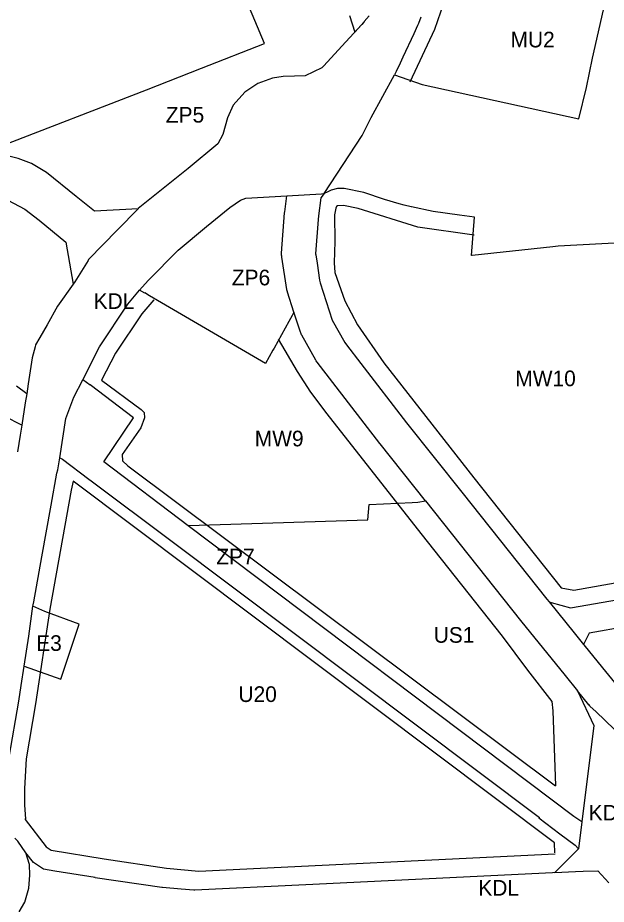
# Model space of a CAD drawing. Extents: x 7428103 to 7431580, y 5545880 to 5549002.
# Drawn here: x 7429131.7 to 7429340.3, y 5547973.7 to 5548288 of the extents above; entities that cross this region are included whole.
import ezdxf

# ---------------------------------------------------------------- set-up
doc = ezdxf.new("R2010")
doc.units = 0
for name, color, linetype in [('CZ_L_linie rozgraniczające tereny o różnym przeznaczeniu oraz różnych warunkach ich zabudowy i zagospodarowania', 7, 'Continuous'), ('CZ_L_maksymalne nieprzekraczalne linie zabudowy', 7, 'Continuous'), ('CZ_L_opisy_linie rozgraniczające tereny o różnym przeznaczeniu oraz różnych warunkach ich zabudowy i zagospodarowania', 7, 'Continuous')]:
    doc.layers.add(name, color=color, linetype=linetype)

msp = doc.modelspace()

# ---------------------------------------------------------------- linework, layer by layer
at = {"layer": 'CZ_L_linie rozgraniczające tereny o różnym przeznaczeniu oraz różnych warunkach ich zabudowy i zagospodarowania'}
for p, q in [((7429219.15, 5548278.95), (7429209.95, 5548300.95)), ((7429335.47, 5548273.67), (7429339.93, 5548293.42)), ((7429249.28, 5548288.79), (7429251.17, 5548282.96)), ((7429256.3, 5548288.71), (7429254.54, 5548286.65)), ((7429274.55, 5548288.21), (7429273.79, 5548285.99)), ((7429253.66, 5548285.6), (7429246.64, 5548277.96)), ((7429251.17, 5548282.96), (7429254.47, 5548286.56)), ((7429254.46, 5548286.46), (7429253.66, 5548285.6)), ((7429254.47, 5548286.56), (7429254.46, 5548286.46)), ((7429254.54, 5548286.65), (7429254.47, 5548286.56)), ((7429273.44, 5548285.25), (7429272.08, 5548282.34)), ((7429273.79, 5548285.99), (7429273.44, 5548285.25)), ((7429272.08, 5548282.34), (7429268.23, 5548274.09)), ((7429196.87, 5548270.18), (7429219.15, 5548278.95)), ((7429246.64, 5548277.96), (7429240.18, 5548270.95)), ((7429268.23, 5548274.09), (7429267.23, 5548271.95)), ((7429333.33, 5548263.33), (7429335.47, 5548273.67)), ((7429177.42, 5548262.52), (7429196.87, 5548270.18)), ((7429239.53, 5548270.24), (7429233.62, 5548267.48)), ((7429240.18, 5548270.95), (7429239.53, 5548270.24)), ((7429267.23, 5548271.95), (7429265.83, 5548268.95)), ((7429222.05, 5548266.67), (7429216.84, 5548264.76)), ((7429225.79, 5548267.17), (7429222.05, 5548266.67)), ((7429229.87, 5548267.33), (7429225.79, 5548267.17)), ((7429233.62, 5548267.48), (7429229.87, 5548267.33)), ((7429257.04, 5548252.68), (7429265.27, 5548267.75)), ((7429265.83, 5548268.95), (7429265.27, 5548267.75)), ((7429265.27, 5548267.75), (7429275.08, 5548264.33)), ((7429216.84, 5548264.76), (7429212.19, 5548261.67)), ((7429275.08, 5548264.33), (7429330.57, 5548252.2)), ((7429330.57, 5548252.2), (7429333.33, 5548263.33)), ((7429124.64, 5548242.13), (7429177.42, 5548262.52)), ((7429212.19, 5548261.67), (7429208.11, 5548257.07)), ((7429208.11, 5548257.07), (7429206.08, 5548252.55)), ((7429206.08, 5548252.55), (7429204.44, 5548246.68)), ((7429253.81, 5548246.23), (7429257.04, 5548252.68)), ((7429204.44, 5548246.68), (7429202.7, 5548243.37)), ((7429240.31, 5548225.7), (7429253.81, 5548246.23)), ((7429202.7, 5548243.37), (7429192.13, 5548234.58)), ((7429131.95, 5548238.17), (7429125.06, 5548239.73)), ((7429136.62, 5548236.39), (7429131.95, 5548238.17)), ((7429141.88, 5548233.19), (7429136.62, 5548236.39)), ((7429192.13, 5548234.58), (7429174.45, 5548220.38)), ((7429152.47, 5548224.68), (7429141.88, 5548233.19)), ((7429227.16, 5548224.92), (7429239.38, 5548225.64)), ((7429240.31, 5548225.7), (7429239.17, 5548224.19)), ((7429239.38, 5548225.64), (7429240.31, 5548225.7)), ((7429241.42, 5548226.24), (7429240.31, 5548225.7)), ((7429242.77, 5548226.9), (7429241.42, 5548226.24)), ((7429245.07, 5548227.45), (7429242.77, 5548226.9)), ((7429247.45, 5548227.46), (7429245.07, 5548227.45)), ((7429254.38, 5548226.13), (7429247.45, 5548227.46)), ((7429261.71, 5548223.63), (7429254.38, 5548226.13)), ((7429128.22, 5548223.31), (7429134.26, 5548220.14)), ((7429158.94, 5548219.41), (7429152.47, 5548224.68)), ((7429206.88, 5548220.73), (7429210.66, 5548223.39)), ((7429210.66, 5548223.39), (7429212.6, 5548224.07)), ((7429212.6, 5548224.07), (7429227.16, 5548224.92)), ((7429226.37, 5548219.22), (7429227.16, 5548224.92)), ((7429239.17, 5548224.19), (7429238.28, 5548217.75)), ((7429266.93, 5548222.09), (7429261.71, 5548223.63)), ((7429268.72, 5548221.56), (7429266.93, 5548222.09)), ((7429134.26, 5548220.14), (7429139.28, 5548216.27)), ((7429174.39, 5548220.32), (7429158.94, 5548219.41)), ((7429174.39, 5548220.32), (7429167.07, 5548212.8)), ((7429174.45, 5548220.38), (7429174.39, 5548220.32)), ((7429198.61, 5548214.05), (7429206.88, 5548220.73)), ((7429225.27, 5548204.54), (7429226.32, 5548218.83)), ((7429226.32, 5548218.83), (7429226.33, 5548218.93)), ((7429226.33, 5548218.93), (7429226.37, 5548219.22)), ((7429271.24, 5548221.03), (7429268.72, 5548221.56)), ((7429271.25, 5548221.03), (7429271.24, 5548221.03)), ((7429278.94, 5548219.37), (7429271.25, 5548221.03)), ((7429288.33, 5548218.06), (7429278.94, 5548219.37)), ((7429139.28, 5548216.27), (7429148.82, 5548208.44)), ((7429238.18, 5548216.48), (7429237.29, 5548204.34)), ((7429238.28, 5548217.75), (7429238.18, 5548216.48)), ((7429293.57, 5548217.32), (7429288.33, 5548218.06)), ((7429292.59, 5548203.71), (7429293.57, 5548217.32)), ((7429167.07, 5548212.8), (7429156.85, 5548202.3)), ((7429188.64, 5548205.64), (7429198.61, 5548214.05)), ((7429148.82, 5548208.44), (7429151.36, 5548193.54)), ((7429321.42, 5548206.8), (7429292.85, 5548203.74)), ((7429323.27, 5548206.99), (7429321.42, 5548206.8)), ((7429351.88, 5548208.53), (7429323.27, 5548206.99)), ((7429177.92, 5548194.9), (7429188.64, 5548205.64)), ((7429225.26, 5548204.24), (7429225.27, 5548204.54)), ((7429225.26, 5548203.85), (7429225.26, 5548204.24)), ((7429225.29, 5548203.46), (7429225.26, 5548203.85)), ((7429225.33, 5548203.17), (7429225.29, 5548203.46)), ((7429227.13, 5548191.66), (7429225.33, 5548203.17)), ((7429237.29, 5548204.34), (7429237.35, 5548203.95)), ((7429237.35, 5548203.95), (7429237.82, 5548200.96)), ((7429292.85, 5548203.74), (7429292.59, 5548203.71)), ((7429156.66, 5548202), (7429151.96, 5548194.39)), ((7429156.85, 5548202.3), (7429156.66, 5548202)), ((7429237.82, 5548200.96), (7429238.75, 5548195.01)), ((7429151.36, 5548193.54), (7429145.83, 5548185.78)), ((7429151.96, 5548194.39), (7429151.36, 5548193.54)), ((7429174.95, 5548191.41), (7429177.92, 5548194.9)), ((7429238.75, 5548195.01), (7429238.91, 5548193.99)), ((7429238.91, 5548193.99), (7429243.16, 5548180.86)), ((7429170.77, 5548186.51), (7429174.95, 5548191.41)), ((7429176.77, 5548190.35), (7429174.95, 5548191.41)), ((7429176.83, 5548190.45), (7429176.77, 5548190.35)), ((7429178.44, 5548189.4), (7429176.83, 5548190.45)), ((7429227.15, 5548191.56), (7429227.13, 5548191.66)), ((7429227.23, 5548191.18), (7429227.15, 5548191.56)), ((7429227.33, 5548190.8), (7429227.23, 5548191.18)), ((7429227.35, 5548190.74), (7429227.33, 5548190.8)), ((7429229.65, 5548183.65), (7429227.35, 5548190.74)), ((7429219.52, 5548165.45), (7429178.44, 5548189.4)), ((7429145.83, 5548185.78), (7429142.18, 5548179.15)), ((7429160.74, 5548171.37), (7429170.77, 5548186.51)), ((7429229, 5548182.44), (7429227.81, 5548180.3)), ((7429229.65, 5548183.65), (7429229, 5548182.44)), ((7429231.93, 5548176.6), (7429229.65, 5548183.65)), ((7429142.18, 5548179.15), (7429139.59, 5548174.69)), ((7429227.81, 5548180.3), (7429222.57, 5548170.88)), ((7429243.16, 5548180.86), (7429247.62, 5548172.91)), ((7429139.59, 5548174.69), (7429138.09, 5548172.03)), ((7429232.04, 5548176.29), (7429231.93, 5548176.6)), ((7429232.19, 5548175.93), (7429232.04, 5548176.29)), ((7429232.37, 5548175.58), (7429232.19, 5548175.93)), ((7429232.41, 5548175.52), (7429232.37, 5548175.58)), ((7429237.37, 5548166.66), (7429232.41, 5548175.52)), ((7429138.09, 5548172.03), (7429137.9, 5548171.31)), ((7429247.62, 5548172.91), (7429248.24, 5548172.1)), ((7429248.24, 5548172.1), (7429253.39, 5548165.43)), ((7429137.9, 5548171.31), (7429136.85, 5548167.43)), ((7429154.76, 5548159.67), (7429160.74, 5548171.37)), ((7429222.16, 5548170.19), (7429219.52, 5548165.45)), ((7429222.57, 5548170.88), (7429222.16, 5548170.19)), ((7429136.85, 5548167.43), (7429135.46, 5548158.26)), ((7429237.53, 5548166.39), (7429237.37, 5548166.66)), ((7429237.75, 5548166.06), (7429237.53, 5548166.39)), ((7429237.85, 5548165.93), (7429237.75, 5548166.06)), ((7429260.1, 5548137.07), (7429237.85, 5548165.93)), ((7429253.39, 5548165.43), (7429269.58, 5548144.43)), ((7429151.58, 5548153.46), (7429154.76, 5548159.67)), ((7429157.39, 5548157.79), (7429154.76, 5548159.67)), ((7429134.92, 5548154.74), (7429131.28, 5548157.46)), ((7429135.46, 5548158.26), (7429134.92, 5548154.74)), ((7429157.43, 5548157.86), (7429157.39, 5548157.79)), ((7429172.75, 5548146.17), (7429157.43, 5548157.86)), ((7429134.92, 5548154.74), (7429134.43, 5548151.49)), ((7429148.74, 5548145.95), (7429151.58, 5548153.46)), ((7429134.43, 5548151.49), (7429133.18, 5548143.55)), ((7429133.18, 5548143.55), (7429127.17, 5548146.62)), ((7429133.18, 5548143.55), (7429132.62, 5548140.01)), ((7429146.63, 5548132.03), (7429148.74, 5548145.95)), ((7429162.3, 5548130.54), (7429172.75, 5548146.17)), ((7429269.58, 5548144.43), (7429289.14, 5548119.8)), ((7429132.62, 5548140.01), (7429131.7, 5548134.17)), ((7429260.16, 5548137), (7429260.1, 5548137.07)), ((7429276.27, 5548116.71), (7429260.16, 5548137)), ((7429145.98, 5548127.79), (7429146.63, 5548132.03)), ((7429146.63, 5548132.03), (7429147.11, 5548131.74)), ((7429147.11, 5548131.74), (7429147.13, 5548131.73)), ((7429147.13, 5548131.73), (7429147.57, 5548131.48)), ((7429147.57, 5548131.48), (7429156.89, 5548124.48)), ((7429145.62, 5548126.54), (7429145.98, 5548127.79)), ((7429192.14, 5548107.87), (7429162.3, 5548130.54)), ((7429143.59, 5548115.26), (7429145.62, 5548126.54)), ((7429156.89, 5548124.48), (7429157.79, 5548123.81)), ((7429157.79, 5548123.81), (7429185.95, 5548102.65)), ((7429289.14, 5548119.8), (7429319.28, 5548081.85)), ((7429140.27, 5548096.83), (7429143.59, 5548115.26)), ((7429255.88, 5548109.98), (7429256.24, 5548115.41)), ((7429256.24, 5548115.41), (7429271.54, 5548116.17)), ((7429271.54, 5548116.17), (7429273.58, 5548116.25)), ((7429273.58, 5548116.25), (7429276.27, 5548116.71)), ((7429276.27, 5548116.71), (7429309.91, 5548074.36)), ((7429192.28, 5548107.99), (7429255.88, 5548109.98)), ((7429192.16, 5548107.88), (7429192.14, 5548107.87)), ((7429192.16, 5548107.88), (7429192.28, 5548107.99)), ((7429328.88, 5548004.86), (7429192.16, 5548107.88)), ((7429185.95, 5548102.65), (7429316.69, 5548004.45)), ((7429137.41, 5548080.93), (7429140.27, 5548096.83)), ((7429137.2, 5548079.81), (7429137.41, 5548080.93)), ((7429319.28, 5548081.85), (7429320.05, 5548080.91)), ((7429320.05, 5548080.91), (7429328.95, 5548069.92)), ((7429320.05, 5548080.91), (7429320.85, 5548080.68)), ((7429320.85, 5548080.68), (7429327.62, 5548078.82)), ((7429327.62, 5548078.82), (7429347.33, 5548082.28)), ((7429135.62, 5548068.81), (7429137.15, 5548079.45)), ((7429137.15, 5548079.45), (7429137.2, 5548079.81)), ((7429141.4, 5548077.55), (7429137.15, 5548079.45)), ((7429153.55, 5548073.02), (7429141.4, 5548077.55)), ((7429383.33, 5548078.47), (7429334.25, 5548069.83)), ((7429309.91, 5548074.36), (7429309.94, 5548074.32)), ((7429309.94, 5548074.32), (7429325.71, 5548054.85)), ((7429146.99, 5548053.54), (7429153.55, 5548073.02)), ((7429134.01, 5548058.16), (7429135.62, 5548068.81)), ((7429328.95, 5548069.92), (7429328.95, 5548069.92)), ((7429328.95, 5548069.92), (7429332.32, 5548065.77)), ((7429334.25, 5548069.83), (7429332.32, 5548065.77)), ((7429332.32, 5548065.77), (7429332.36, 5548065.71)), ((7429332.36, 5548065.71), (7429338.98, 5548057.54)), ((7429132.96, 5548051.26), (7429134.01, 5548058.16)), ((7429134.01, 5548058.16), (7429146.99, 5548053.54)), ((7429338.98, 5548057.54), (7429343.25, 5548052.27)), ((7429325.71, 5548054.85), (7429330.19, 5548049.33)), ((7429132.12, 5548045.7), (7429132.96, 5548051.26)), ((7429334.17, 5548044.42), (7429330.19, 5548049.33)), ((7429330.19, 5548049.33), (7429335.88, 5548037.07)), ((7429128.73, 5548025.84), (7429132.12, 5548045.7)), ((7429334.22, 5548044.36), (7429334.17, 5548044.42)), ((7429334.48, 5548044.06), (7429334.22, 5548044.36)), ((7429334.68, 5548043.87), (7429334.48, 5548044.06)), ((7429336.61, 5548042.02), (7429334.68, 5548043.87)), ((7429346.57, 5548032.47), (7429336.61, 5548042.02)), ((7429335.88, 5548037.07), (7429331.62, 5548002.9)), ((7429316.69, 5548004.45), (7429316.42, 5548004.29)), ((7429316.42, 5548004.29), (7429323.88, 5547998.7)), ((7429331.62, 5548002.9), (7429328.88, 5548004.86)), ((7429331.62, 5548002.9), (7429330.43, 5547993.35)), ((7429323.88, 5547998.7), (7429329.29, 5547994.62)), ((7429131.78, 5547996.01), (7429130.7, 5547997.11)), ((7429134.67, 5547991.98), (7429131.78, 5547996.01)), ((7429330.43, 5547993.35), (7429322.06, 5547984.92)), ((7429329.29, 5547994.62), (7429330.43, 5547993.35)), ((7429135.86, 5547987.85), (7429134.67, 5547991.98)), ((7429137.33, 5547988.53), (7429134.67, 5547991.98)), ((7429136.02, 5547984.04), (7429135.86, 5547987.85)), ((7429140.86, 5547986.15), (7429137.33, 5547988.53)), ((7429144.92, 5547985.47), (7429140.86, 5547986.15)), ((7429135.63, 5547979.44), (7429136.02, 5547984.04)), ((7429144.93, 5547985.47), (7429144.92, 5547985.47)), ((7429159.18, 5547983.13), (7429144.93, 5547985.47)), ((7429159.2, 5547983.13), (7429159.18, 5547983.13)), ((7429159.23, 5547983.12), (7429159.2, 5547983.13)), ((7429182.87, 5547979.65), (7429159.23, 5547983.12)), ((7429321.23, 5547984.88), (7429233.85, 5547980.6)), ((7429322.06, 5547984.92), (7429321.23, 5547984.88)), ((7429322.06, 5547984.92), (7429329.42, 5547985.28)), ((7429329.42, 5547985.28), (7429332.13, 5547985.41)), ((7429332.13, 5547985.41), (7429337.38, 5547985.6)), ((7429337.38, 5547985.6), (7429341.26, 5547981.26)), ((7429233.85, 5547980.6), (7429194.49, 5547978.67)), ((7429134.31, 5547974.42), (7429135.63, 5547979.44)), ((7429183.01, 5547979.63), (7429182.87, 5547979.65)), ((7429183.02, 5547979.63), (7429183.01, 5547979.63)), ((7429189.71, 5547979.05), (7429183.02, 5547979.63)), ((7429189.72, 5547979.05), (7429189.71, 5547979.05)), ((7429194.16, 5547978.68), (7429189.72, 5547979.05)), ((7429194.31, 5547978.67), (7429194.16, 5547978.68)), ((7429194.49, 5547978.67), (7429194.31, 5547978.67)), ((7429132.25, 5547970.99), (7429134.31, 5547974.42))]:
    msp.add_line(p, q, dxfattribs=at)
at = {"layer": 'CZ_L_maksymalne nieprzekraczalne linie zabudowy'}
for points in [[(7429341.66, 5548475.02), (7429335.21, 5548451.88), (7429320.74, 5548397.16), (7429310.09, 5548363.49), (7429299.06, 5548334.66), (7429287.9, 5548308.54), (7429279.42, 5548283.92), (7429270.71, 5548265.21)], [(7429293.52, 5548210.93), (7429273.54, 5548213.77), (7429252.34, 5548220.38), (7429247.2, 5548221.45), (7429245.11, 5548221.36), (7429244.71, 5548221.13), (7429244.47, 5548220.47), (7429244.03, 5548218.15), (7429244.17, 5548208.68), (7429243.95, 5548201.14), (7429244.11, 5548197.66), (7429247.65, 5548187.7), (7429252.16, 5548179.18), (7429261.51, 5548165.67), (7429293.45, 5548124.9), (7429324.37, 5548085.93), (7429328.8, 5548085.12), (7429380.66, 5548094.24)], [(7429179.96, 5548188.04), (7429175.68, 5548183.03), (7429166.41, 5548169.07), (7429161.44, 5548159.57), (7429175.47, 5548149.18), (7429176.56, 5548148.04), (7429176.64, 5548146.17), (7429175.37, 5548142.63), (7429168.73, 5548133.12), (7429168.82, 5548130.98), (7429170.77, 5548129.21), (7429322.33, 5548015.73)], [(7429322.4, 5548015.68), (7429321.47, 5548042.31), (7429321.17, 5548045.57), (7429312.51, 5548056.71), (7429303.51, 5548068.81), (7429274.7, 5548105.12), (7429241.4, 5548147.56), (7429235.65, 5548155.28), (7429230.92, 5548162.6), (7429224.17, 5548174.1)], [(7429322.12, 5547991.9), (7429321.97, 5547995.52), (7429151.33, 5548123.73), (7429150.64, 5548120.54), (7429143.06, 5548078.37), (7429138.05, 5548044.77), (7429134.72, 5548025.31), (7429134.13, 5548014.69), (7429134.14, 5548008.85), (7429134.47, 5548004.02)], [(7429134.41, 5548004.06), (7429134.43, 5548003.77), (7429141.84, 5547994.1), (7429143.63, 5547992.87), (7429162.41, 5547989.77), (7429184.41, 5547986.54), (7429195.87, 5547985.46), (7429322.27, 5547991.61)]]:
    msp.add_lwpolyline(points, dxfattribs=at)

# ---------------------------------------------------------------- texts
at = {"layer": 'CZ_L_opisy_linie rozgraniczające tereny o różnym przeznaczeniu oraz różnych warunkach ich zabudowy i zagospodarowania'}
for s, p in [('MU2', (7429306.4, 5548277.53)), ('ZP5', (7429184.22, 5548250.86)), ('ZP6', (7429207.62, 5548193.15)), ('KDL', (7429158.64, 5548184.79)), ('MW10', (7429308.09, 5548157.39)), ('MW9', (7429215.75, 5548136.06)), ('ZP7', (7429202.09, 5548094.19)), ('US1', (7429279.17, 5548066.42)), ('E3', (7429138.28, 5548063.53)), ('U20', (7429209.96, 5548045.42)), ('KDL', (7429334.12, 5548003.4)), ('KDL', (7429294.99, 5547976.74))]:
    msp.add_text(s, height=5.549, dxfattribs=at).set_placement(p)

doc.saveas('drawing.dxf')
